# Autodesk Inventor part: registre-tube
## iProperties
Author: chr
Created: 2001-06
Part Number: registre-tube
Material: Par défaut
Document SubType Name: Modélisation
Designer: chr
Control State: 0
Master: False
Checked Out: False
PropertySet Name: Design Tracking Control
Shininess: 21.0
PropertySet Name: _Private Model Information
Length Units: 11269
Angle Units: 11286
Time Units: 11279
Mass Units: 11290
Length Display Precision: 3
Angle Display Precision: 2
Compacted: False
Density: 0.0
Volumn: 0.0
Area: 0.0
PropertySet Name: Model Information
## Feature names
1. Extrusion1
2. Extrusion2
